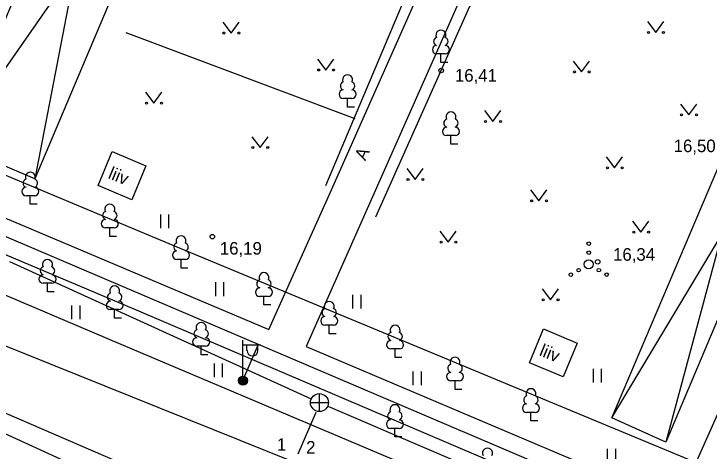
# Model space of a CAD drawing. Extents: x 713540 to 713867, y 6589774 to 6590061.
# Drawn here: x 713575.55 to 713614.29, y 6589968.22 to 6589992.56 of the extents above; entities that cross this region are included whole.
import ezdxf

# ---------------------------------------------------------------- set-up
doc = ezdxf.new("R2010")
doc.units = 0
for name, color, linetype in [('AED', 7, 'Continuous'), ('HALJASTUS', 7, 'Continuous'), ('HOONE', 7, 'Continuous'), ('HOONEDET', 7, 'Continuous'), ('KKAEV', 7, 'Continuous'), ('KORGUS', 7, 'Continuous'), ('KTRASS', 7, 'Continuous'), ('MPKAABEL', 7, 'Continuous'), ('POST', 7, 'Continuous'), ('PUU', 7, 'Continuous'), ('RAJATIS', 7, 'Continuous'), ('TEE', 7, 'Continuous'), ('TORU NR', 7, 'Continuous'), ('VTRASS', 7, 'Continuous')]:
    doc.layers.add(name, color=color, linetype=linetype)

msp = doc.modelspace()

# ---------------------------------------------------------------- linework, layer by layer
at = {"layer": 'AED'}
msp.add_lwpolyline([(713636.535, 6590004.444), (713635.778, 6590001.331), (713631.008, 6589989.639), (713620.691, 6589964.611), (713584.43, 6589979.666), (713562.034, 6589989.021), (713563.098, 6589991.568)], dxfattribs=at)
at = {"layer": 'HALJASTUS'}
for p, q in [((713587.187, 6589992.107), (713587.65, 6589991.5)), ((713587.65, 6589991.5), (713588.096, 6589992.107)), ((713610.847, 6589992.137), (713611.31, 6589991.53)), ((713611.31, 6589991.53), (713611.756, 6589992.137)), ((713592.467, 6589990.047), (713592.93, 6589989.44)), ((713592.93, 6589989.44), (713593.376, 6589990.047)), ((713606.717, 6589989.937), (713607.18, 6589989.33)), ((713607.18, 6589989.33), (713607.626, 6589989.937)), ((713582.877, 6589988.207), (713583.34, 6589987.6)), ((713583.34, 6589987.6), (713583.786, 6589988.207)), ((713612.687, 6589987.547), (713613.15, 6589986.94)), ((713613.15, 6589986.94), (713613.596, 6589987.547)), ((713601.767, 6589987.177), (713602.23, 6589986.57)), ((713602.23, 6589986.57), (713602.676, 6589987.177)), ((713588.797, 6589985.727), (713589.26, 6589985.12)), ((713589.26, 6589985.12), (713589.706, 6589985.727)), ((713608.557, 6589984.607), (713609.02, 6589984)), ((713609.02, 6589984), (713609.466, 6589984.607)), ((713597.447, 6589983.957), (713597.91, 6589983.35)), ((713597.91, 6589983.35), (713598.356, 6589983.957)), ((713604.337, 6589982.767), (713604.8, 6589982.16)), ((713604.8, 6589982.16), (713605.246, 6589982.767)), ((713583.715, 6589981.392), (713583.715, 6589980.631)), ((713584.17, 6589981.392), (713584.17, 6589980.631)), ((713610.027, 6589981.017), (713610.49, 6589980.41)), ((713610.49, 6589980.41), (713610.936, 6589981.017)), ((713599.287, 6589980.467), (713599.75, 6589979.86)), ((713599.75, 6589979.86), (713600.196, 6589980.467)), ((713586.771, 6589977.617), (713586.771, 6589976.855)), ((713587.226, 6589977.617), (713587.226, 6589976.855)), ((713604.977, 6589977.247), (713605.44, 6589976.64)), ((713605.44, 6589976.64), (713605.886, 6589977.247)), ((713594.423, 6589976.916), (713594.423, 6589976.155)), ((713594.878, 6589976.916), (713594.878, 6589976.155)), ((713578.762, 6589976.332), (713578.762, 6589975.57)), ((713579.217, 6589976.332), (713579.217, 6589975.57)), ((713586.703, 6589973.093), (713586.703, 6589972.331)), ((713587.158, 6589973.093), (713587.158, 6589972.331)), ((713607.822, 6589972.791), (713607.822, 6589972.03)), ((713608.277, 6589972.791), (713608.277, 6589972.03)), ((713597.783, 6589972.649), (713597.783, 6589971.888)), ((713598.238, 6589972.649), (713598.238, 6589971.888)), ((713608.614, 6589968.353), (713608.614, 6589967.592)), ((713609.069, 6589968.353), (713609.069, 6589967.592))]:
    msp.add_line(p, q, dxfattribs=at)
for points in [[(713580.24, 6590010.9), (713587.901, 6590007.59), (713600.769, 6590001.615), (713592.902, 6589982.996)], [(713602.638, 6589996.811), (713595.693, 6589981.239)], [(713581.782, 6589991.521), (713594.54, 6589986.74)]]:
    msp.add_lwpolyline(points, dxfattribs=at)
for centre, radius in [((713587.249, 6589991.5), 0.055), ((713588.078, 6589991.5), 0.055), ((713610.909, 6589991.53), 0.055), ((713611.738, 6589991.53), 0.055), ((713592.529, 6589989.44), 0.055), ((713593.358, 6589989.44), 0.055), ((713606.779, 6589989.33), 0.055), ((713607.608, 6589989.33), 0.055), ((713582.939, 6589987.6), 0.055), ((713583.768, 6589987.6), 0.055), ((713612.749, 6589986.94), 0.055), ((713613.578, 6589986.94), 0.055), ((713601.829, 6589986.57), 0.055), ((713602.658, 6589986.57), 0.055), ((713588.859, 6589985.12), 0.055), ((713589.688, 6589985.12), 0.055), ((713608.619, 6589984), 0.055), ((713609.448, 6589984), 0.055), ((713597.509, 6589983.35), 0.055), ((713598.338, 6589983.35), 0.055), ((713604.399, 6589982.16), 0.055), ((713605.228, 6589982.16), 0.055), ((713610.089, 6589980.41), 0.055), ((713610.918, 6589980.41), 0.055), ((713599.349, 6589979.86), 0.055), ((713600.178, 6589979.86), 0.055), ((713607.58, 6589979.77), 0.1), ((713607.58, 6589979.27), 0.1), ((713607.58, 6589978.62), 0.25), ((713606.58, 6589978.045), 0.1), ((713607.015, 6589978.295), 0.1), ((713608.145, 6589978.295), 0.1), ((713608.58, 6589978.045), 0.1), ((713605.039, 6589976.64), 0.055), ((713605.868, 6589976.64), 0.055)]:
    msp.add_circle(centre, radius, dxfattribs=at)
at = {"layer": 'HOONE'}
for points in [[(713585.853, 6590004.995), (713576.715, 6589983.374), (713572.132, 6589985.32), (713581.271, 6590006.941), (713585.853, 6590004.995)], [(713621.015, 6589990.338), (713611.877, 6589968.717), (713608.872, 6589970.068), (713618.021, 6589991.61), (713621.015, 6589990.338)]]:
    msp.add_lwpolyline(points, dxfattribs=at)
at = {"layer": 'HOONEDET'}
for p, q in [((713581.271, 6590006.941), (713576.715, 6589983.374)), ((713572.132, 6589985.32), (713585.853, 6590004.995)), ((713618.021, 6589991.61), (713611.877, 6589968.717)), ((713608.872, 6589970.068), (713621.015, 6589990.338))]:
    msp.add_line(p, q, dxfattribs=at)
at = {"layer": 'KKAEV'}
for p, q in [((713592.573, 6589970.417), (713592.573, 6589971.417)), ((713592.073, 6589970.917), (713593.073, 6589970.917))]:
    msp.add_line(p, q, dxfattribs=at)
msp.add_circle((713592.573, 6589970.917), 0.5, dxfattribs=at)
at = {"layer": 'KORGUS'}
for centre in [(713599.36, 6589989.41), (713586.6, 6589980.16), (713608.08, 6589978.76)]:
    msp.add_circle(centre, 0.125, dxfattribs=at)
at = {"layer": 'KTRASS'}
msp.add_line((713591.114, 6589967.621), (713573.259, 6589974.798), dxfattribs=at)
for points in [[(713575.301, 6589978.771), (713592.118, 6589971.124)], [(713592.375, 6589970.376), (713591.377, 6589968.046)], [(713593.033, 6589970.72), (713619.367, 6589959.438)]]:
    msp.add_lwpolyline(points, dxfattribs=at)
at = {"layer": 'MPKAABEL'}
for points in [[(713673.84, 6589926.98), (713652.92, 6589935.82), (713594.68, 6589960.2), (713571.23, 6589970.92), (713558.27, 6589976.81), (713545.498, 6589982.044)], [(713588.309, 6589972.144), (713589.17, 6589974.165)]]:
    msp.add_lwpolyline(points, dxfattribs=at)
at = {"layer": 'POST'}
for p, q in [((713588.309, 6589972.394), (713588.309, 6589974.394)), ((713588.309, 6589974.144), (713589.309, 6589974.144)), ((713588.535, 6589973.823), (713588.535, 6589974.144)), ((713589.148, 6589973.823), (713589.148, 6589974.144))]:
    msp.add_line(p, q, dxfattribs=at)
for radius in [0.25, 0.225, 0.2, 0.175, 0.15, 0.125, 0.1, 0.075, 0.05, 0.025]:
    msp.add_circle((713588.309, 6589972.144), radius, dxfattribs=at)
msp.add_arc((713588.842, 6589973.823), 0.306, 180, 0, dxfattribs=at)
at = {"layer": 'PUU'}
for p, q in [((713599.58, 6589990.335), (713599.1, 6589990.335)), ((713599.34, 6589989.86), (713599.34, 6589990.335)), ((713599.72, 6589989.86), (713599.34, 6589989.86)), ((713594.38, 6589987.855), (713593.9, 6589987.855)), ((713594.14, 6589987.38), (713594.14, 6589987.855)), ((713594.52, 6589987.38), (713594.14, 6589987.38)), ((713600.14, 6589985.785), (713599.66, 6589985.785)), ((713599.9, 6589985.31), (713599.9, 6589985.785)), ((713600.28, 6589985.31), (713599.9, 6589985.31)), ((713576.7, 6589982.435), (713576.22, 6589982.435)), ((713576.46, 6589981.96), (713576.46, 6589982.435)), ((713576.84, 6589981.96), (713576.46, 6589981.96)), ((713581.13, 6589980.645), (713580.65, 6589980.645)), ((713580.89, 6589980.17), (713580.89, 6589980.645)), ((713581.27, 6589980.17), (713580.89, 6589980.17)), ((713585.099, 6589978.889), (713584.619, 6589978.889)), ((713584.859, 6589978.414), (713584.859, 6589978.889)), ((713585.239, 6589978.414), (713584.859, 6589978.414)), ((713577.656, 6589977.561), (713577.176, 6589977.561)), ((713577.416, 6589977.086), (713577.416, 6589977.561)), ((713577.796, 6589977.086), (713577.416, 6589977.086)), ((713589.72, 6589976.835), (713589.24, 6589976.835)), ((713589.48, 6589976.36), (713589.48, 6589976.835)), ((713589.86, 6589976.36), (713589.48, 6589976.36)), ((713581.399, 6589976.095), (713580.919, 6589976.095)), ((713581.159, 6589975.62), (713581.159, 6589976.095)), ((713581.539, 6589975.62), (713581.159, 6589975.62)), ((713593.359, 6589975.232), (713592.879, 6589975.232)), ((713593.119, 6589974.757), (713593.119, 6589975.232)), ((713593.499, 6589974.757), (713593.119, 6589974.757)), ((713586.22, 6589974.059), (713585.74, 6589974.059)), ((713585.98, 6589973.584), (713585.98, 6589974.059)), ((713597.029, 6589973.904), (713596.549, 6589973.904)), ((713596.789, 6589973.429), (713596.789, 6589973.904)), ((713586.36, 6589973.584), (713585.98, 6589973.584)), ((713597.169, 6589973.429), (713596.789, 6589973.429)), ((713600.367, 6589972.127), (713599.887, 6589972.127)), ((713600.127, 6589971.652), (713600.127, 6589972.127)), ((713600.507, 6589971.652), (713600.127, 6589971.652)), ((713604.598, 6589970.37), (713604.118, 6589970.37)), ((713604.358, 6589969.895), (713604.358, 6589970.37)), ((713604.738, 6589969.895), (713604.358, 6589969.895)), ((713597.017, 6589969.479), (713596.537, 6589969.479)), ((713596.777, 6589969.004), (713596.777, 6589969.479)), ((713597.157, 6589969.004), (713596.777, 6589969.004))]:
    msp.add_line(p, q, dxfattribs=at)
for centre, radius, start, end in [((713599.34, 6589991.38), 0.277, 332.5799, 207.4201), ((713599.17, 6589991.033), 0.233, 109.0217, 253.1415), ((713599.51, 6589991.033), 0.233, 286.8508, 70.9859), ((713599.103, 6589990.572), 0.238, 90.0016, 269.3953), ((713599.577, 6589990.572), 0.238, 270.6047, 89.9984), ((713594.14, 6589988.9), 0.277, 332.5799, 207.4201), ((713593.97, 6589988.553), 0.233, 109.0217, 253.1415), ((713594.31, 6589988.553), 0.233, 286.8508, 70.9859), ((713593.903, 6589988.092), 0.238, 90.0016, 269.3953), ((713594.377, 6589988.092), 0.238, 270.6047, 89.9984), ((713599.9, 6589986.83), 0.277, 332.5799, 207.4201), ((713599.73, 6589986.483), 0.233, 109.0217, 253.1415), ((713600.07, 6589986.483), 0.233, 286.8508, 70.9859), ((713599.663, 6589986.022), 0.238, 90.0016, 269.3953), ((713600.137, 6589986.022), 0.238, 270.6047, 89.9984), ((713576.46, 6589983.48), 0.277, 332.5799, 207.4201), ((713576.29, 6589983.133), 0.233, 109.0217, 253.1415), ((713576.63, 6589983.133), 0.233, 286.8508, 70.9859), ((713576.223, 6589982.672), 0.238, 90.0016, 269.3953), ((713576.697, 6589982.672), 0.238, 270.6047, 89.9984), ((713580.89, 6589981.69), 0.277, 332.5799, 207.4201), ((713580.72, 6589981.343), 0.233, 109.0217, 253.1415), ((713581.06, 6589981.343), 0.233, 286.8508, 70.9859), ((713580.653, 6589980.882), 0.238, 90.0016, 269.3953), ((713581.127, 6589980.882), 0.238, 270.6047, 89.9984), ((713584.859, 6589979.934), 0.277, 332.5799, 207.4201), ((713584.689, 6589979.586), 0.233, 109.0217, 253.1415), ((713585.029, 6589979.586), 0.233, 286.8508, 70.9859), ((713584.622, 6589979.126), 0.238, 90.0016, 269.3953), ((713585.097, 6589979.126), 0.238, 270.6047, 89.9984), ((713577.416, 6589978.606), 0.277, 332.5799, 207.4201), ((713577.246, 6589978.259), 0.233, 109.0217, 253.1415), ((713577.586, 6589978.259), 0.233, 286.8508, 70.9859), ((713589.48, 6589977.88), 0.277, 332.5799, 207.4201), ((713577.179, 6589977.799), 0.238, 90.0016, 269.3953), ((713577.654, 6589977.799), 0.238, 270.6047, 89.9984), ((713589.31, 6589977.533), 0.233, 109.0217, 253.1415), ((713589.65, 6589977.533), 0.233, 286.8508, 70.9859), ((713581.159, 6589977.14), 0.277, 332.5799, 207.4201), ((713580.989, 6589976.793), 0.233, 109.0217, 253.1415), ((713581.329, 6589976.793), 0.233, 286.8508, 70.9859), ((713589.243, 6589977.072), 0.238, 90.0016, 269.3953), ((713589.717, 6589977.072), 0.238, 270.6047, 89.9984), ((713580.921, 6589976.333), 0.238, 90.0016, 269.3953), ((713581.396, 6589976.333), 0.238, 270.6047, 89.9984), ((713593.119, 6589976.277), 0.277, 332.5799, 207.4201), ((713592.949, 6589975.929), 0.233, 109.0217, 253.1415), ((713593.289, 6589975.929), 0.233, 286.8508, 70.9859), ((713592.882, 6589975.469), 0.238, 90.0016, 269.3953), ((713593.357, 6589975.469), 0.238, 270.6047, 89.9984), ((713585.98, 6589975.104), 0.277, 332.5799, 207.4201), ((713596.789, 6589974.949), 0.277, 332.5799, 207.4201), ((713585.81, 6589974.756), 0.233, 109.0217, 253.1415), ((713586.15, 6589974.756), 0.233, 286.8508, 70.9859), ((713596.619, 6589974.602), 0.233, 109.0217, 253.1415), ((713596.959, 6589974.602), 0.233, 286.8508, 70.9859), ((713585.743, 6589974.296), 0.238, 90.0016, 269.3953), ((713586.218, 6589974.296), 0.238, 270.6047, 89.9984), ((713596.552, 6589974.142), 0.238, 90.0016, 269.3953), ((713597.027, 6589974.142), 0.238, 270.6047, 89.9984), ((713600.127, 6589973.172), 0.277, 332.5799, 207.4201), ((713599.957, 6589972.825), 0.233, 109.0217, 253.1415), ((713600.297, 6589972.825), 0.233, 286.8508, 70.9859), ((713599.889, 6589972.365), 0.238, 90.0016, 269.3953), ((713600.364, 6589972.365), 0.238, 270.6047, 89.9984), ((713604.358, 6589971.415), 0.277, 332.5799, 207.4201), ((713604.188, 6589971.068), 0.233, 109.0217, 253.1415), ((713604.529, 6589971.068), 0.233, 286.8508, 70.9859), ((713596.777, 6589970.524), 0.277, 332.5799, 207.4201), ((713604.121, 6589970.608), 0.238, 90.0016, 269.3953), ((713604.596, 6589970.608), 0.238, 270.6047, 89.9984), ((713596.607, 6589970.177), 0.233, 109.0217, 253.1415), ((713596.947, 6589970.177), 0.233, 286.8508, 70.9859), ((713596.54, 6589969.717), 0.238, 90.0016, 269.3953), ((713597.015, 6589969.717), 0.238, 270.6047, 89.9984), ((713601.937, 6589968.103), 0.277, 332.5799, 207.4201)]:
    msp.add_arc(centre, radius, start, end, dxfattribs=at)
at = {"layer": 'RAJATIS'}
for points in [[(713582.902, 6589984.102), (713582.123, 6589982.214), (713580.245, 6589983.009), (713581.024, 6589984.897), (713582.902, 6589984.102)], [(713606.929, 6589974.234), (713606.15, 6589972.346), (713604.272, 6589973.141), (713605.051, 6589975.029), (713606.929, 6589974.234)]]:
    msp.add_lwpolyline(points, dxfattribs=at)
at = {"layer": 'TEE'}
for points in [[(713614.57, 6589999.34), (713613.707, 6589997.19), (713603.922, 6590001.326), (713591.825, 6589974.045), (713621.261, 6589961.576), (713622.688, 6589963.147), (713630.481, 6589979.098), (713635.632, 6589979.743), (713638.264, 6589986.883), (713641.401, 6589995.818), (713639.191, 6590011.645), (713635.853, 6590032.559), (713631.194, 6590060.636)], [(713539.965, 6589996.032), (713549.561, 6589991.973), (713558.372, 6589988.246), (713589.758, 6589974.996), (713593.238, 6589982.776), (713601.739, 6590001.879), (713576.031, 6590013.158), (713583.714, 6590030.669), (713591.243, 6590044.583), (713591.106, 6590056.602)], [(713539.965, 6589996.032), (713549.561, 6589991.973), (713558.372, 6589988.246), (713589.758, 6589974.996), (713593.238, 6589982.776), (713601.739, 6590001.879), (713576.031, 6590013.158), (713583.714, 6590030.669), (713591.243, 6590044.583), (713591.106, 6590056.602)], [(713539.965, 6589994.014), (713540.025, 6589993.989), (713549.069, 6589990.154), (713558.517, 6589986.148), (713582.352, 6589976.078), (713640.058, 6589951.475), (713653.623, 6589945.708)], [(713539.965, 6589991.821), (713546.483, 6589989.051), (713550.123, 6589987.505), (713581.64, 6589974.119), (713603.369, 6589964.935), (713626.923, 6589954.938), (713652.713, 6589944.022), (713653.863, 6589943.948), (713654.374, 6589944.858), (713653.623, 6589945.708)], [(713549.337, 6589991.146), (713616.72, 6589962.42), (713657.09, 6589945.22)]]:
    msp.add_lwpolyline(points, dxfattribs=at)
at = {"layer": 'VTRASS'}
for points in [[(713539.965, 6589985.5), (713582.013, 6589967.334)], [(713608.676, 6589956.662), (713621.51, 6589985.36), (713642.92, 6589975.12), (713654.41, 6589964.42)]]:
    msp.add_lwpolyline(points, dxfattribs=at)

# ---------------------------------------------------------------- texts
at = {"layer": 'KORGUS'}
for s, p in [('16,41', (713600.122, 6589988.79)), ('16,50', (713612.311, 6589984.865)), ('16,19', (713587.022, 6589979.16)), ('16,34', (713608.934, 6589978.82))]:
    msp.add_text(s, height=0.7, dxfattribs=at).set_placement(p)
at = {"layer": 'RAJATIS'}
for p in [(713580.748, 6589983.429), (713604.776, 6589973.561)]:
    msp.add_text('liiv', height=0.7, rotation=337.6475, dxfattribs=at).set_placement(p)
at = {"layer": 'TEE'}
msp.add_text('A', height=0.7, rotation=64.6049, dxfattribs=at).set_placement((713595.13, 6589984.35))
at = {"layer": 'TORU NR'}
for s, p in [('1', (713590.204, 6589968.238)), ('2', (713591.83, 6589968.079))]:
    msp.add_text(s, height=0.7, dxfattribs=at).set_placement(p)

doc.saveas('drawing.dxf')
